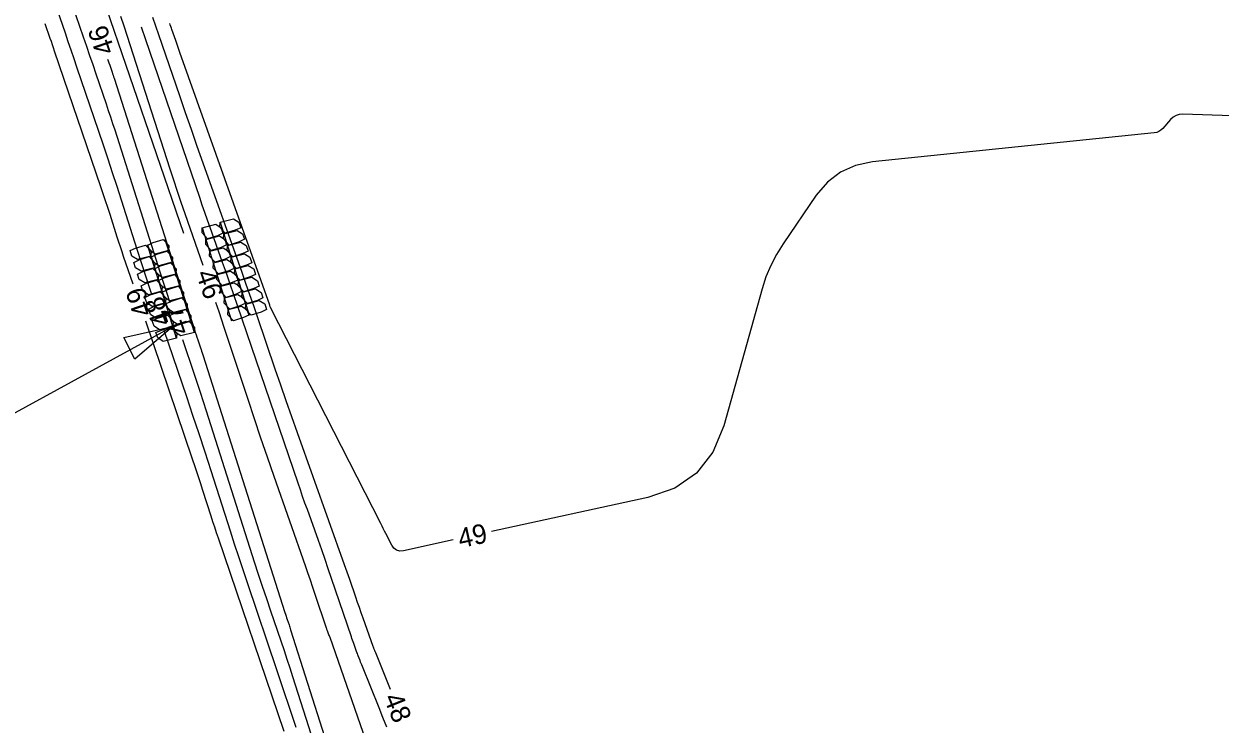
# Model space of a CAD drawing. Extents: x 2384780 to 2405861, y 547869 to 573706.
# Drawn here: x 2391803.7 to 2391926.2, y 552815.8 to 552887.6 of the extents above; entities that cross this region are included whole.
import ezdxf

# ---------------------------------------------------------------- set-up
doc = ezdxf.new("R2010")
doc.units = 0
for name, color, linetype in [('Breaklines', 7, 'Continuous'), ('Old_Level_5', 7, 'Continuous'), ('Old_Level_60', 7, 'Continuous')]:
    doc.layers.add(name, color=color, linetype=linetype)

# ---------------------------------------------------------------- blocks, each defined once
blk = doc.blocks.new('RRA')
at = {"layer": 'Breaklines'}
for p, q in [((0, 0.078), (0.2, 0.078)), ((0, 0.04), (0.2, 0.04)), ((0.2, -0.04), (0, -0.04)), ((0.2, -0.078), (0, -0.078))]:
    blk.add_line(p, q, dxfattribs=at)
for points in [[(0.0235, 0.115), (0.025, 0.103), (0.025, 0.0815), (0.01, 0.0745), (0, 0.078), (0.0015, 0.1065), (0.01175, 0.115), (0.0235, 0.115)], [(0.0485, 0.115), (0.05025, 0.103), (0.05025, 0.0815), (0.035, 0.0745), (0.025, 0.078), (0.02675, 0.1065), (0.037, 0.115), (0.0485, 0.115)], [(0.07375, 0.115), (0.0755, 0.103), (0.0755, 0.0815), (0.06025, 0.0745), (0.05025, 0.078), (0.052, 0.1065), (0.062, 0.115), (0.07375, 0.115)], [(0.099, 0.115), (0.1005, 0.103), (0.1005, 0.0815), (0.0855, 0.0745), (0.0755, 0.078), (0.077, 0.1065), (0.087, 0.115), (0.099, 0.115)], [(0.124, 0.115), (0.1255, 0.103), (0.1255, 0.0815), (0.1105, 0.0745), (0.1005, 0.078), (0.102, 0.1065), (0.11225, 0.115), (0.124, 0.115)], [(0.149, 0.115), (0.15075, 0.103), (0.15075, 0.0815), (0.1355, 0.0745), (0.1255, 0.078), (0.12725, 0.1065), (0.1375, 0.115), (0.149, 0.115)], [(0.17425, 0.115), (0.176, 0.103), (0.176, 0.0815), (0.16075, 0.0745), (0.15075, 0.078), (0.1525, 0.1065), (0.1625, 0.115), (0.17425, 0.115)], [(0.1995, 0.115), (0.201, 0.103), (0.201, 0.0815), (0.186, 0.0745), (0.176, 0.078), (0.1775, 0.1065), (0.1875, 0.115), (0.1995, 0.115)], [(0.0235, 0.077), (0.025, 0.065), (0.025, 0.0435), (0.01, 0.0365), (0, 0.04), (0.0015, 0.0685), (0.01175, 0.077), (0.0235, 0.077)], [(0.0485, 0.077), (0.05025, 0.065), (0.05025, 0.0435), (0.035, 0.0365), (0.025, 0.04), (0.02675, 0.0685), (0.037, 0.077), (0.0485, 0.077)], [(0.07375, 0.077), (0.0755, 0.065), (0.0755, 0.0435), (0.06025, 0.0365), (0.05025, 0.04), (0.052, 0.0685), (0.062, 0.077), (0.07375, 0.077)], [(0.099, 0.077), (0.1005, 0.065), (0.1005, 0.0435), (0.0855, 0.0365), (0.0755, 0.04), (0.077, 0.0685), (0.087, 0.077), (0.099, 0.077)], [(0.124, 0.077), (0.1255, 0.065), (0.1255, 0.0435), (0.1105, 0.0365), (0.1005, 0.04), (0.102, 0.0685), (0.11225, 0.077), (0.124, 0.077)], [(0.149, 0.077), (0.15075, 0.065), (0.15075, 0.0435), (0.1355, 0.0365), (0.1255, 0.04), (0.12725, 0.0685), (0.1375, 0.077), (0.149, 0.077)], [(0.17425, 0.077), (0.176, 0.065), (0.176, 0.0435), (0.16075, 0.0365), (0.15075, 0.04), (0.1525, 0.0685), (0.1625, 0.077), (0.17425, 0.077)], [(0.1995, 0.077), (0.201, 0.065), (0.201, 0.0435), (0.186, 0.0365), (0.176, 0.04), (0.1775, 0.0685), (0.1875, 0.077), (0.1995, 0.077)], [(0.0005, -0.077), (-0.001, -0.065), (-0.001, -0.0435), (0.014, -0.0365), (0.024, -0.04), (0.0225, -0.0685), (0.0125, -0.077), (0.0005, -0.077)], [(0.02575, -0.077), (0.024, -0.065), (0.024, -0.0435), (0.03925, -0.0365), (0.04925, -0.04), (0.0475, -0.0685), (0.0375, -0.077), (0.02575, -0.077)], [(0.051, -0.077), (0.04925, -0.065), (0.04925, -0.0435), (0.0645, -0.0365), (0.0745, -0.04), (0.07275, -0.0685), (0.0625, -0.077), (0.051, -0.077)], [(0.076, -0.077), (0.0745, -0.065), (0.0745, -0.0435), (0.0895, -0.0365), (0.0995, -0.04), (0.098, -0.0685), (0.08775, -0.077), (0.076, -0.077)], [(0.101, -0.077), (0.0995, -0.065), (0.0995, -0.0435), (0.1145, -0.0365), (0.1245, -0.04), (0.123, -0.0685), (0.113, -0.077), (0.101, -0.077)], [(0.12625, -0.077), (0.1245, -0.065), (0.1245, -0.0435), (0.13975, -0.0365), (0.14975, -0.04), (0.148, -0.0685), (0.138, -0.077), (0.12625, -0.077)], [(0.1515, -0.077), (0.14975, -0.065), (0.14975, -0.0435), (0.165, -0.0365), (0.175, -0.04), (0.17325, -0.0685), (0.163, -0.077), (0.1515, -0.077)], [(0.1765, -0.077), (0.175, -0.065), (0.175, -0.0435), (0.19, -0.0365), (0.2, -0.04), (0.1985, -0.0685), (0.18825, -0.077), (0.1765, -0.077)], [(0.0005, -0.115), (-0.001, -0.103), (-0.001, -0.0815), (0.014, -0.0745), (0.024, -0.078), (0.0225, -0.1065), (0.0125, -0.115), (0.0005, -0.115)], [(0.02575, -0.115), (0.024, -0.103), (0.024, -0.0815), (0.03925, -0.0745), (0.04925, -0.078), (0.0475, -0.1065), (0.0375, -0.115), (0.02575, -0.115)], [(0.051, -0.115), (0.04925, -0.103), (0.04925, -0.0815), (0.0645, -0.0745), (0.0745, -0.078), (0.07275, -0.1065), (0.0625, -0.115), (0.051, -0.115)], [(0.076, -0.115), (0.0745, -0.103), (0.0745, -0.0815), (0.0895, -0.0745), (0.0995, -0.078), (0.098, -0.1065), (0.08775, -0.115), (0.076, -0.115)], [(0.101, -0.115), (0.0995, -0.103), (0.0995, -0.0815), (0.1145, -0.0745), (0.1245, -0.078), (0.123, -0.1065), (0.113, -0.115), (0.101, -0.115)], [(0.12625, -0.115), (0.1245, -0.103), (0.1245, -0.0815), (0.13975, -0.0745), (0.14975, -0.078), (0.148, -0.1065), (0.138, -0.115), (0.12625, -0.115)], [(0.1515, -0.115), (0.14975, -0.103), (0.14975, -0.0815), (0.165, -0.0745), (0.175, -0.078), (0.17325, -0.1065), (0.163, -0.115), (0.1515, -0.115)], [(0.1765, -0.115), (0.175, -0.103), (0.175, -0.0815), (0.19, -0.0745), (0.2, -0.078), (0.1985, -0.1065), (0.18825, -0.115), (0.1765, -0.115)]]:
    blk.add_lwpolyline(points, dxfattribs=at)

msp = doc.modelspace()

# ---------------------------------------------------------------- linework, layer by layer
at = {"layer": 'Breaklines'}
for p, q in [((2391820.056, 552866.099), (2391754.1115, 553058.7325)), ((2391818.95925, 552856.58225), (2391754.64092, 552821.40359))]:
    msp.add_line(p, q, dxfattribs=at)
msp.add_lwpolyline([(2391813.93052, 552855.45339), (2391818.95925, 552856.58225), (2391815.05336, 552853.21973)], close=True, dxfattribs=at)
at = {"layer": 'Old_Level_60'}
for points in [[(2391806.379, 552896.15025), (2391809.7635, 552886.258), (2391810.087, 552885.31175), (2391810.4105, 552884.365), (2391810.7335, 552883.4185), (2391811.05625, 552882.47175), (2391812.11025, 552879.379), (2391812.3345, 552878.71575), (2391812.55525, 552878.05125), (2391812.773, 552877.386), (2391812.9875, 552876.7195), (2391817.86525, 552861.4305), (2391818.2975, 552860.08625), (2391818.64625, 552859.01975)], [(2391806.5015, 552890.75), (2391807.89725, 552886.6705), (2391808.196, 552885.79625), (2391808.49475, 552884.922), (2391808.79325, 552884.04775), (2391809.09125, 552883.17325), (2391811.3325, 552876.59625), (2391811.80925, 552875.18575), (2391812.27925, 552873.773), (2391812.742, 552872.35775), (2391813.198, 552870.9405), (2391815.2495, 552864.51), (2391815.6925, 552863.13325), (2391816.142, 552861.7585), (2391816.598, 552860.386), (2391816.73125, 552859.99125)], [(2391822.057, 552862.82775), (2391820.20675, 552868.124), (2391819.81125, 552869.267), (2391819.42275, 552870.4125), (2391819.04125, 552871.56025), (2391818.667, 552872.71025), (2391813.94775, 552887.3565), (2391813.61575, 552888.343)], [(2391841.24075, 552819.3655), (2391839.72725, 552823.11675), (2391839.7015, 552823.18075), (2391839.67575, 552823.245), (2391839.65025, 552823.30925), (2391839.625, 552823.37375), (2391839.5425, 552823.584), (2391839.525, 552823.629), (2391839.50775, 552823.67425), (2391839.491, 552823.71975), (2391839.4745, 552823.76525), (2391838.43775, 552826.6675), (2391838.245, 552827.2105), (2391838.0545, 552827.754), (2391837.866, 552828.2985), (2391837.67975, 552828.84375), (2391837.07475, 552830.62575), (2391836.94425, 552831.00725), (2391836.8125, 552831.3885), (2391836.67925, 552831.769), (2391836.5445, 552832.149), (2391831.7165, 552845.68725), (2391831.13925, 552847.31475), (2391830.568, 552848.94425), (2391830.0025, 552850.57575), (2391829.44275, 552852.20925), (2391827.624, 552857.5485), (2391827.23225, 552858.69225), (2391826.837, 552859.83425), (2391826.438, 552860.97525), (2391826.035, 552862.11475), (2391822.0555, 552873.31575), (2391821.4475, 552875.03475), (2391820.845, 552876.756), (2391820.24775, 552878.479), (2391819.65575, 552880.20375), (2391817.5125, 552886.4795), (2391817.2065, 552887.36725), (2391816.8955, 552888.2535)], [(2391805.842, 552887.63475), (2391806.35825, 552886.12575), (2391806.46875, 552885.8025), (2391806.57925, 552885.479), (2391806.68975, 552885.1555), (2391806.8, 552884.83225), (2391811.54325, 552870.91225), (2391811.782, 552870.20625), (2391812.01725, 552869.499), (2391812.249, 552868.79075), (2391812.47725, 552868.0815), (2391813.217, 552865.762), (2391813.37675, 552865.2655), (2391813.539, 552864.76975), (2391813.7035, 552864.2745), (2391813.87025, 552863.78025), (2391814.839, 552860.93325)], [(2391840.86275, 552815.518), (2391840.472, 552816.49575), (2391840.079, 552817.4725), (2391838.3625, 552821.72675), (2391838.3015, 552821.878), (2391838.24125, 552822.0295), (2391838.18125, 552822.181), (2391838.1215, 552822.3325), (2391837.92725, 552822.82825), (2391837.886, 552822.9345), (2391837.8455, 552823.04125), (2391837.806, 552823.14825), (2391837.76725, 552823.2555), (2391837.47475, 552824.07425), (2391837.41225, 552824.25), (2391837.35075, 552824.42575), (2391837.28975, 552824.60175), (2391837.2295, 552824.77825), (2391835.20225, 552830.74925), (2391834.86975, 552831.72275), (2391834.5335, 552832.69475), (2391834.1935, 552833.6655), (2391833.84975, 552834.63475), (2391832.72125, 552837.7995), (2391832.4805, 552838.47825), (2391832.24225, 552839.1575), (2391832.0065, 552839.83775), (2391831.77325, 552840.519), (2391825.57125, 552858.72575), (2391825.19375, 552859.8275), (2391824.81275, 552860.928), (2391824.42825, 552862.02725), (2391824.04025, 552863.12525), (2391822.7665, 552866.71), (2391822.49475, 552867.47875), (2391822.2255, 552868.248), (2391821.9585, 552869.01825), (2391821.69375, 552869.7895), (2391816.1735, 552885.95425), (2391815.721, 552887.26725)], [(2391847.66725, 552834.70725), (2391842.55525, 552833.59275), (2391842.18025, 552833.56175), (2391841.85875, 552833.6445), (2391841.591, 552833.84075), (2391841.37725, 552834.1505), (2391840.7665, 552835.348), (2391840.6355, 552835.60475), (2391840.50475, 552835.86125), (2391840.37375, 552836.11775), (2391840.243, 552836.3745), (2391828.98075, 552858.4545), (2391828.966, 552858.4845), (2391828.95225, 552858.515), (2391828.9395, 552858.546), (2391828.92775, 552858.57725), (2391828.87725, 552858.71875), (2391828.87625, 552858.72175), (2391828.87525, 552858.7245), (2391828.87425, 552858.72725), (2391828.8735, 552858.73025), (2391828.87025, 552858.7395), (2391828.8695, 552858.7415), (2391828.86875, 552858.7435), (2391828.86825, 552858.7455), (2391828.8675, 552858.74725), (2391819.66725, 552884.641), (2391819.55825, 552884.94975), (2391819.45, 552885.25875), (2391819.34275, 552885.56825), (2391819.2365, 552885.87775), (2391818.8515, 552887.00475), (2391818.79675, 552887.16425), (2391818.74075, 552887.32325), (2391818.684, 552887.482), (2391818.62625, 552887.6405)], [(2391812.26425, 552883.99075), (2391812.32675, 552883.80825), (2391812.40225, 552883.5865), (2391812.478, 552883.36475), (2391812.725, 552882.64), (2391812.7775, 552882.48475), (2391812.82925, 552882.329), (2391812.88025, 552882.173), (2391812.9305, 552882.017), (2391821.15575, 552856.235), (2391821.2375, 552855.98075), (2391821.3205, 552855.727), (2391821.40475, 552855.4735), (2391821.49, 552855.2205), (2391821.771, 552854.39475), (2391821.831, 552854.2175), (2391821.88975, 552854.04025), (2391821.94775, 552853.8625), (2391822.005, 552853.6845), (2391830.42975, 552827.245), (2391830.48575, 552827.071), (2391830.5425, 552826.897), (2391830.6, 552826.7235), (2391830.65825, 552826.55025), (2391830.8505, 552825.98475), (2391830.89125, 552825.8635), (2391830.93175, 552825.74225), (2391830.97125, 552825.6205), (2391831.0105, 552825.4985), (2391839.717, 552798.1405)], [(2391929.438, 552878.10875), (2391922.3955, 552878.3295), (2391922.037, 552878.3045), (2391921.7105, 552878.2065), (2391921.416, 552878.035), (2391921.153, 552877.7905), (2391920.346, 552876.87175), (2391920.162, 552876.696), (2391919.95625, 552876.563), (2391919.7285, 552876.47225), (2391919.47875, 552876.42425), (2391890.59975, 552873.4455), (2391888.8655, 552873.08975), (2391887.3295, 552872.401), (2391885.992, 552871.37875), (2391884.853, 552870.0235), (2391881.45575, 552865.052), (2391880.7755, 552863.9645), (2391880.19025, 552862.83275), (2391879.70025, 552861.6565), (2391879.30525, 552860.436), (2391875.38125, 552846.3985), (2391874.264, 552843.68325), (2391872.594, 552841.55375), (2391870.3715, 552840.00975), (2391867.596, 552839.05175), (2391851.5755, 552835.55925)], [(2391839.03075, 552813.269), (2391835.046, 552824.68025), (2391835.01175, 552824.77725), (2391834.97625, 552824.8735), (2391834.94, 552824.96975), (2391834.90275, 552825.06525), (2391834.779, 552825.37725), (2391834.753, 552825.44425), (2391834.728, 552825.51175), (2391834.70375, 552825.57925), (2391834.68075, 552825.6475), (2391833.52925, 552829.0975), (2391833.281, 552829.83625), (2391833.0305, 552830.57425), (2391832.7775, 552831.3115), (2391832.52175, 552832.04775), (2391829.322, 552841.2105), (2391828.64075, 552843.17525), (2391827.968, 552845.14325), (2391827.304, 552847.114), (2391826.64875, 552849.08775), (2391824.2125, 552856.47875), (2391823.687, 552858.0615), (2391823.35575, 552859.0445)], [(2391816.1275, 552857.1465), (2391820.93725, 552843.01025), (2391821.20825, 552842.20725), (2391821.4755, 552841.403), (2391821.7385, 552840.5975), (2391821.99775, 552839.79075), (2391822.8385, 552837.153), (2391823.01975, 552836.588), (2391823.204, 552836.02425), (2391823.39075, 552835.46125), (2391823.58025, 552834.899), (2391830.3085, 552815.095)], [(2391818.01725, 552856.20375), (2391820.33775, 552849.38425), (2391820.974, 552847.49925), (2391821.601, 552845.61125), (2391822.21875, 552843.72025), (2391822.82725, 552841.82625), (2391824.8005, 552835.63425), (2391825.22625, 552834.3085), (2391825.6585, 552832.98475), (2391826.097, 552831.663), (2391826.542, 552830.34325), (2391829.609, 552821.3155), (2391830.2615, 552819.3795), (2391830.90475, 552817.44025), (2391831.5385, 552815.498)], [(2391819.91875, 552855.2275), (2391821.11875, 552851.7005), (2391821.43475, 552850.764), (2391821.74625, 552849.826), (2391822.05325, 552848.8865), (2391822.3555, 552847.94575), (2391827.29075, 552832.4575), (2391827.695, 552831.199), (2391828.10525, 552829.9425), (2391828.5215, 552828.688), (2391828.94375, 552827.43525), (2391830.33275, 552823.34675), (2391830.6285, 552822.47), (2391830.91975, 552821.59175), (2391831.20675, 552820.712), (2391831.4895, 552819.831), (2391837.13375, 552802.0955)]]:
    msp.add_lwpolyline(points, dxfattribs=at)

# ---------------------------------------------------------------- block references
at = {"layer": 'Old_Level_5', "xscale": 50, "yscale": 50, "rotation": -72.55106678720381}
msp.add_blockref('RRA', (2391820.056, 552866.099), dxfattribs=at)

# ---------------------------------------------------------------- texts
at = {"layer": 'Old_Level_60'}
for s, rotation, p in [('46', 108.8862028, (2391813.04225, 552884.80625)), ('46', 288.9464306, (2391821.285, 552862.01325)), ('49', 108.7908778, (2391816.90675, 552857.9605)), ('48', 108.7555889, (2391818.8035, 552856.99475)), ('47', 108.5477528, (2391820.68075, 552856.08125)), ('49', 12.2982917, (2391848.38825, 552833.84075)), ('48', 291.9748694, (2391840.49925, 552818.531))]:
    msp.add_text(s, height=2, rotation=rotation, dxfattribs=at).set_placement(p)

doc.saveas('drawing.dxf')
